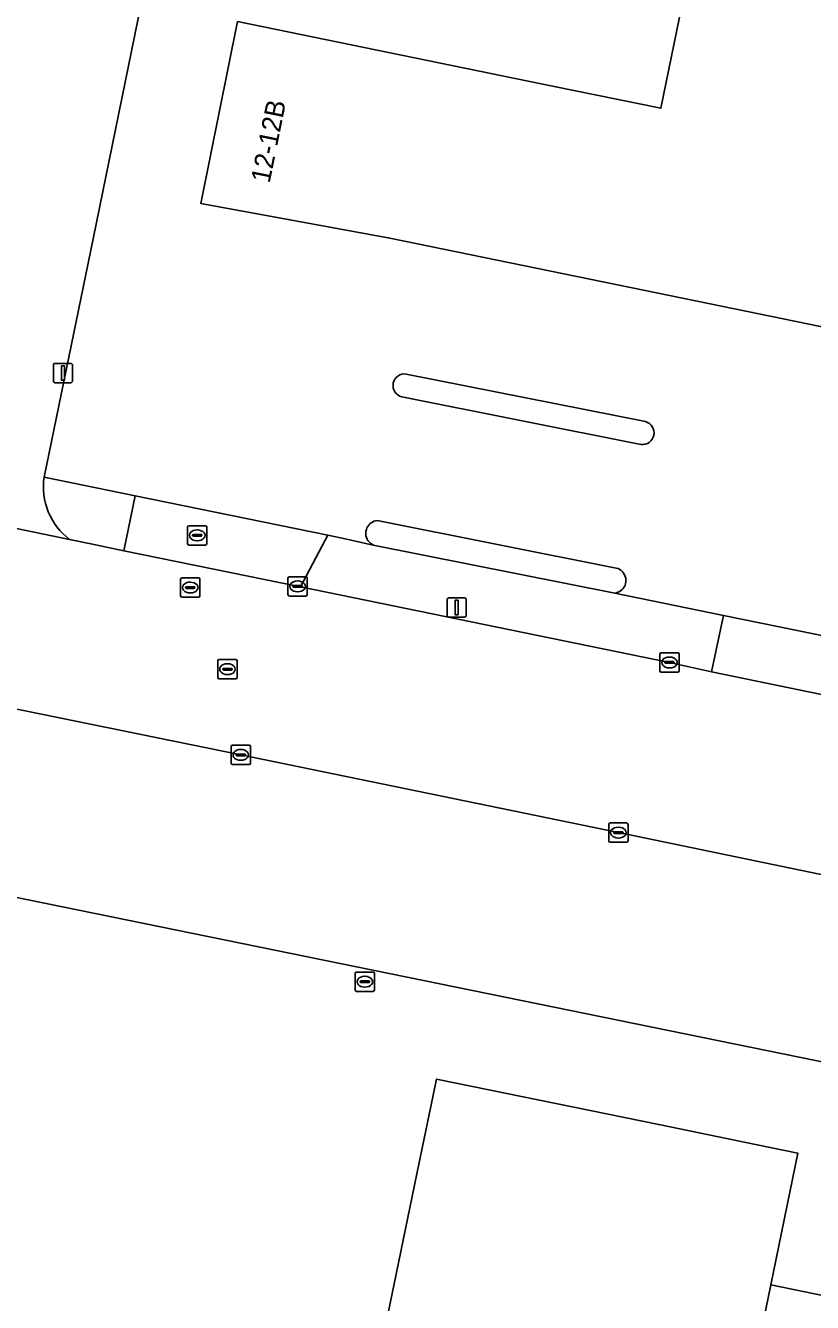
# Model space of a CAD drawing. Extents: x 157692 to 159674, y 381452 to 383291.
# Drawn here: x 158709.4 to 158750.1, y 382274.1 to 382340.2 of the extents above; entities that cross this region are included whole.
import ezdxf

# ---------------------------------------------------------------- set-up
doc = ezdxf.new("R2010")
doc.units = 0
for name, color, linetype in [('IMGEO_Brandkraan', 7, 'Continuous'), ('IMGEO_Erf', 7, 'Continuous'), ('IMGEO_Kolk', 7, 'Continuous'), ('IMGEO_Lichtmast', 7, 'Continuous'), ('IMGEO_Pand', 7, 'Continuous'), ('IMGEO_Pand_nummerreeks', 7, 'Continuous'), ('IMGEO_Rijbaan_lokaal_open', 7, 'Continuous'), ('IMGEO_Rioolput', 7, 'Continuous'), ('IMGEO_Verkeerseiland_open', 7, 'Continuous'), ('IMGEO_Voetpad_open', 7, 'Continuous')]:
    doc.layers.add(name, color=color, linetype=linetype)

msp = doc.modelspace()

# ---------------------------------------------------------------- linework, layer by layer
at = {"layer": 'IMGEO_Brandkraan'}
for p, q in [((158717.808, 382313.38), (158717.808, 382314.232)), ((158717.883, 382314.306), (158718.735, 382314.306)), ((158718.809, 382314.232), (158718.809, 382313.38)), ((158718.067, 382313.8), (158718.067, 382313.812)), ((158718.505, 382313.763), (158718.107, 382313.763)), ((158718.11, 382313.849), (158718.508, 382313.849)), ((158718.319, 382313.526), (158718.294, 382313.526)), ((158718.296, 382314.086), (158718.321, 382314.086)), ((158718.551, 382313.812), (158718.551, 382313.8)), ((158718.735, 382313.306), (158717.883, 382313.306))]:
    msp.add_line(p, q, dxfattribs=at)
for points in [[(158717.808, 382313.38), (158717.808, 382314.232)], [(158717.883, 382314.306), (158718.735, 382314.306)], [(158718.809, 382314.232), (158718.809, 382313.38)], [(158718.735, 382313.306), (158717.883, 382313.306)]]:
    msp.add_lwpolyline(points, dxfattribs=at)
for centre, radius, start, end in [((158717.885, 382314.23), 0.0765, 91.55205, 178.44795), ((158717.885, 382314.23), 0.0765, 91.55205, 178.44795), ((158718.733, 382314.23), 0.0765, 1.55205, 88.44795), ((158718.733, 382314.23), 0.0765, 1.55205, 88.44795), ((158718.107, 382313.809), 0.0403, 85.87752, 175.75265), ((158718.104, 382313.799), 0.0366, 178.93798, 274.71019), ((158718.508, 382313.806), 0.043, 264.86636, 352.45326), ((158718.512, 382313.811), 0.0386, 1.73085, 96.63898), ((158717.885, 382313.382), 0.0765, 181.55205, 268.44795), ((158717.885, 382313.382), 0.0765, 181.55205, 268.44795), ((158718.733, 382313.382), 0.0765, 271.55205, 358.44795), ((158718.733, 382313.382), 0.0765, 271.55205, 358.44795)]:
    msp.add_arc(centre, radius, start, end, dxfattribs=at)
for centre, major_axis, ratio, start_param, end_param in [((158718.295, 382313.806), (-0.387, 0.002), 0.722429, 4.712389, 7.853982), ((158718.32, 382313.806), (-0.39, 0.002), 0.717154, 1.570796, 4.712389)]:
    msp.add_ellipse(centre, major_axis=major_axis, ratio=ratio, start_param=start_param, end_param=end_param, dxfattribs=at)
at = {"layer": 'IMGEO_Erf'}
for points in [[(158720.044, 382364.008), (158712.928, 382329.134), (158710.395, 382316.819), (158715.098, 382315.854), (158725.053, 382313.813), (158725.797, 382313.66), (158727.41, 382313.293)], [(158766.252, 382340.884), (158764.298, 382331.343), (158768.72, 382330.438), (158767.848, 382326.179), (158766.845, 382321.28), (158762.998, 382322.068), (158763.854, 382326.248), (158755.16, 382328.028), (158754.302, 382323.838), (158744.14, 382325.919), (158728.259, 382329.17), (158718.497, 382330.96), (158720.398, 382340.369)], [(158729.115, 382322.147), (158741.475, 382319.685)], [(158741.24, 382318.508), (158728.88, 382320.97)], [(158703.868, 382232.929), (158737.91, 382225.935), (158740.836, 382240.44), (158722.149, 382244.289), (158723.325, 382250), (158729.667, 382280.789), (158730.675, 382285.686), (158742.158, 382283.335), (158747.254, 382282.292), (158749.35, 382281.863), (158747.95, 382275.046), (158756.482, 382273.294), (158758.758, 382284.334), (158774.797, 382281.051), (158774.915, 382281.626), (158583.923, 382320.599)], [(158727.607, 382314.575), (158739.967, 382312.114)], [(158739.897, 382310.815), (158745.516, 382309.667), (158754.049, 382307.922), (158763.74, 382305.941), (158825.695, 382293.283), (158865.561, 382285.172), (158872.186, 382283.72), (158876.329, 382282.962), (158882.131, 382281.773), (158888.158, 382280.537), (158988.039, 382260.114), (159000, 382257.67), (159006.103, 382256.423), (159011.658, 382255.288), (159018.046, 382253.981), (159023.028, 382252.988), (159037.803, 382250), (159039.91, 382249.574), (159043.144, 382248.92), (159043.356, 382248.877), (159043.484, 382248.846), (159053.13, 382246.78), (159055.84, 382246.213), (159072.286, 382242.773)]]:
    msp.add_lwpolyline(points, dxfattribs=at)
for centre, radius, start, end in [((158729.028, 382321.552), 0.601, 81.70547, 255.71211), ((158741.32, 382319.104), 0.601, 262.31937, 75.09822), ((158727.691, 382313.906), 0.674, 97.15339, 212.90377), ((158728.126, 382314.407), 1.324, 220.89476, 237.27648), ((158739.805, 382311.471), 0.663, 305.17046, 75.86444), ((158739.665, 382311.832), 1.043, 282.87012, 300.0498)]:
    msp.add_arc(centre, radius, start, end, dxfattribs=at)
at = {"layer": 'IMGEO_Kolk'}
for p, q in [((158722.996, 382310.741), (158722.996, 382311.593)), ((158723.071, 382311.667), (158723.923, 382311.667)), ((158723.997, 382311.593), (158723.997, 382310.741)), ((158723.255, 382311.161), (158723.255, 382311.173)), ((158723.693, 382311.124), (158723.295, 382311.124)), ((158723.298, 382311.21), (158723.696, 382311.21)), ((158723.507, 382310.887), (158723.482, 382310.887)), ((158723.484, 382311.447), (158723.509, 382311.447)), ((158723.739, 382311.173), (158723.739, 382311.161)), ((158723.923, 382310.667), (158723.071, 382310.667)), ((158742.218, 382306.806), (158742.218, 382307.658)), ((158742.293, 382307.732), (158743.145, 382307.732)), ((158743.219, 382307.658), (158743.219, 382306.806)), ((158742.477, 382307.226), (158742.477, 382307.238)), ((158742.915, 382307.189), (158742.517, 382307.189)), ((158742.52, 382307.275), (158742.918, 382307.275)), ((158742.729, 382306.952), (158742.704, 382306.952)), ((158742.706, 382307.512), (158742.731, 382307.512)), ((158742.961, 382307.238), (158742.961, 382307.226)), ((158743.145, 382306.732), (158742.293, 382306.732)), ((158720.132, 382302.955), (158720.984, 382302.955)), ((158720.057, 382302.029), (158720.057, 382302.881)), ((158720.316, 382302.449), (158720.316, 382302.461)), ((158720.754, 382302.412), (158720.356, 382302.412)), ((158720.359, 382302.498), (158720.757, 382302.498)), ((158720.545, 382302.735), (158720.57, 382302.735)), ((158720.8, 382302.461), (158720.8, 382302.449)), ((158721.058, 382302.881), (158721.058, 382302.029)), ((158720.984, 382301.955), (158720.132, 382301.955)), ((158720.568, 382302.175), (158720.543, 382302.175)), ((158739.575, 382298.008), (158739.575, 382298.86)), ((158739.65, 382298.934), (158740.502, 382298.934)), ((158739.834, 382298.428), (158739.834, 382298.44)), ((158740.272, 382298.391), (158739.874, 382298.391)), ((158739.877, 382298.477), (158740.275, 382298.477)), ((158740.063, 382298.714), (158740.088, 382298.714)), ((158740.318, 382298.44), (158740.318, 382298.428)), ((158740.576, 382298.86), (158740.576, 382298.008)), ((158740.502, 382297.934), (158739.65, 382297.934)), ((158740.086, 382298.154), (158740.061, 382298.154))]:
    msp.add_line(p, q, dxfattribs=at)
for points in [[(158722.996, 382310.741), (158722.996, 382311.593)], [(158723.071, 382311.667), (158723.923, 382311.667)], [(158723.997, 382311.593), (158723.997, 382310.741)], [(158723.923, 382310.667), (158723.071, 382310.667)], [(158742.218, 382306.806), (158742.218, 382307.658)], [(158742.293, 382307.732), (158743.145, 382307.732)], [(158743.219, 382307.658), (158743.219, 382306.806)], [(158743.145, 382306.732), (158742.293, 382306.732)], [(158720.132, 382302.955), (158720.984, 382302.955)], [(158720.057, 382302.029), (158720.057, 382302.881)], [(158721.058, 382302.881), (158721.058, 382302.029)], [(158720.984, 382301.955), (158720.132, 382301.955)], [(158739.575, 382298.008), (158739.575, 382298.86)], [(158739.65, 382298.934), (158740.502, 382298.934)], [(158740.576, 382298.86), (158740.576, 382298.008)], [(158740.502, 382297.934), (158739.65, 382297.934)]]:
    msp.add_lwpolyline(points, dxfattribs=at)
for centre, radius, start, end in [((158723.073, 382311.591), 0.0765, 91.55205, 178.44795), ((158723.073, 382311.591), 0.0765, 91.55205, 178.44795), ((158723.921, 382311.591), 0.0765, 1.55205, 88.44795), ((158723.921, 382311.591), 0.0765, 1.55205, 88.44795), ((158723.295, 382311.17), 0.0403, 85.87752, 175.75265), ((158723.292, 382311.16), 0.0366, 178.93798, 274.71019), ((158723.696, 382311.167), 0.043, 264.86636, 352.45326), ((158723.7, 382311.172), 0.0386, 1.73085, 96.63898), ((158723.073, 382310.743), 0.0765, 181.55205, 268.44795), ((158723.073, 382310.743), 0.0765, 181.55205, 268.44795), ((158723.921, 382310.743), 0.0765, 271.55205, 358.44795), ((158723.921, 382310.743), 0.0765, 271.55205, 358.44795), ((158742.295, 382307.656), 0.0765, 91.55205, 178.44795), ((158742.295, 382307.656), 0.0765, 91.55205, 178.44795), ((158743.143, 382307.656), 0.0765, 1.55205, 88.44795), ((158743.143, 382307.656), 0.0765, 1.55205, 88.44795), ((158742.517, 382307.235), 0.0403, 85.87752, 175.75265), ((158742.514, 382307.225), 0.0366, 178.93798, 274.71019), ((158742.918, 382307.232), 0.043, 264.86636, 352.45326), ((158742.922, 382307.237), 0.0386, 1.73085, 96.63898), ((158742.295, 382306.808), 0.0765, 181.55205, 268.44795), ((158742.295, 382306.808), 0.0765, 181.55205, 268.44795), ((158743.143, 382306.808), 0.0765, 271.55205, 358.44795), ((158743.143, 382306.808), 0.0765, 271.55205, 358.44795), ((158720.134, 382302.879), 0.0765, 91.55205, 178.44795), ((158720.134, 382302.879), 0.0765, 91.55205, 178.44795), ((158720.982, 382302.879), 0.0765, 1.55205, 88.44795), ((158720.982, 382302.879), 0.0765, 1.55205, 88.44795), ((158720.356, 382302.458), 0.0403, 85.87752, 175.75265), ((158720.353, 382302.448), 0.0366, 178.93798, 274.71019), ((158720.757, 382302.455), 0.043, 264.86636, 352.45326), ((158720.761, 382302.46), 0.0386, 1.73085, 96.63898), ((158720.134, 382302.031), 0.0765, 181.55205, 268.44795), ((158720.134, 382302.031), 0.0765, 181.55205, 268.44795), ((158720.982, 382302.031), 0.0765, 271.55205, 358.44795), ((158720.982, 382302.031), 0.0765, 271.55205, 358.44795), ((158739.652, 382298.858), 0.0765, 91.55205, 178.44795), ((158739.652, 382298.858), 0.0765, 91.55205, 178.44795), ((158739.874, 382298.437), 0.0403, 85.87752, 175.75265), ((158739.871, 382298.427), 0.0366, 178.93798, 274.71019), ((158740.275, 382298.434), 0.043, 264.86636, 352.45326), ((158740.279, 382298.439), 0.0386, 1.73085, 96.63898), ((158740.5, 382298.858), 0.0765, 1.55205, 88.44795), ((158740.5, 382298.858), 0.0765, 1.55205, 88.44795), ((158739.652, 382298.01), 0.0765, 181.55205, 268.44795), ((158739.652, 382298.01), 0.0765, 181.55205, 268.44795), ((158740.5, 382298.01), 0.0765, 271.55205, 358.44795), ((158740.5, 382298.01), 0.0765, 271.55205, 358.44795)]:
    msp.add_arc(centre, radius, start, end, dxfattribs=at)
for centre, major_axis, ratio, start_param, end_param in [((158723.483, 382311.167), (-0.387, 0.002), 0.722429, 4.712389, 7.853982), ((158723.508, 382311.167), (-0.39, 0.002), 0.717154, 1.570796, 4.712389), ((158742.705, 382307.232), (-0.387, 0.002), 0.722429, 4.712389, 7.853982), ((158742.73, 382307.232), (-0.39, 0.002), 0.717154, 1.570796, 4.712389), ((158720.544, 382302.455), (-0.387, 0.002), 0.722429, 4.712389, 7.853982), ((158720.569, 382302.455), (-0.39, 0.002), 0.717154, 1.570796, 4.712389), ((158740.062, 382298.434), (-0.387, 0.002), 0.722429, 4.712389, 7.853982), ((158740.087, 382298.434), (-0.39, 0.002), 0.717154, 1.570796, 4.712389)]:
    msp.add_ellipse(centre, major_axis=major_axis, ratio=ratio, start_param=start_param, end_param=end_param, dxfattribs=at)
at = {"layer": 'IMGEO_Lichtmast'}
for p, q in [((158710.874, 382321.797), (158710.874, 382322.597)), ((158710.874, 382322.597), (158710.874, 382321.797)), ((158710.974, 382322.697), (158711.764, 382322.697)), ((158711.764, 382322.697), (158710.974, 382322.697)), ((158711.864, 382322.597), (158711.864, 382321.797)), ((158711.864, 382321.797), (158711.864, 382322.597)), ((158711.764, 382321.697), (158710.974, 382321.697)), ((158710.974, 382321.697), (158711.764, 382321.697)), ((158731.223, 382309.676), (158731.223, 382310.476)), ((158731.223, 382310.476), (158731.223, 382309.676)), ((158731.323, 382310.576), (158732.113, 382310.576)), ((158732.113, 382310.576), (158731.323, 382310.576)), ((158732.213, 382310.476), (158732.213, 382309.676)), ((158732.213, 382309.676), (158732.213, 382310.476)), ((158732.113, 382309.576), (158731.323, 382309.576)), ((158731.323, 382309.576), (158732.113, 382309.576))]:
    msp.add_line(p, q, dxfattribs=at)
for points in [[(158711.294, 382322.572), (158711.444, 382322.572), (158711.444, 382321.822), (158711.294, 382321.822), (158711.294, 382322.572)], [(158731.643, 382310.451), (158731.793, 382310.451), (158731.793, 382309.701), (158731.643, 382309.701), (158731.643, 382310.451)]]:
    msp.add_lwpolyline(points, dxfattribs=at)
for centre, start, end in [((158710.974, 382322.597), 90, 180), ((158710.974, 382322.597), 90, 180), ((158711.764, 382322.597), 0, 90), ((158711.764, 382322.597), 360, 90), ((158710.974, 382321.797), 180, 270), ((158710.974, 382321.797), 180, 270), ((158711.764, 382321.797), 270, 0), ((158711.764, 382321.797), 270, 0), ((158731.323, 382310.476), 90, 180), ((158731.323, 382310.476), 90, 180), ((158732.113, 382310.476), 0, 90), ((158732.113, 382310.476), 360, 90), ((158731.323, 382309.676), 180, 270), ((158731.323, 382309.676), 180, 270), ((158732.113, 382309.676), 270, 0), ((158732.113, 382309.676), 270, 0)]:
    msp.add_arc(centre, 0.1, start, end, dxfattribs=at)
at = {"layer": 'IMGEO_Pand'}
for points in [[(158766.252, 382340.884), (158744.215, 382345.401), (158742.265, 382335.888), (158736.753, 382337.018), (158720.398, 382340.369), (158718.497, 382330.96), (158728.259, 382329.17), (158744.14, 382325.919), (158754.302, 382323.838), (158755.16, 382328.028), (158763.854, 382326.248), (158762.998, 382322.068), (158766.845, 382321.28), (158767.848, 382326.179), (158768.72, 382330.438), (158764.298, 382331.343)], [(158747.95, 382275.046), (158749.35, 382281.863), (158747.254, 382282.292), (158742.158, 382283.335), (158730.675, 382285.686), (158729.667, 382280.789), (158723.325, 382250), (158722.149, 382244.289), (158740.836, 382240.44), (158742.801, 382250), (158744.243, 382257.017)], [(158747.95, 382275.046), (158744.243, 382257.017), (158752.766, 382255.271), (158752.1, 382252.041), (158762.079, 382250), (158768.445, 382248.698), (158768.711, 382250), (158774.171, 382276.675), (158775.174, 382281.573), (158774.915, 382281.626), (158774.797, 382281.051), (158758.758, 382284.334), (158756.482, 382273.294)]]:
    msp.add_lwpolyline(points, close=True, dxfattribs=at)
msp.add_lwpolyline([(158720.398, 382340.369), (158736.753, 382337.018), (158742.265, 382335.888), (158744.215, 382345.401)], dxfattribs=at)
at = {"layer": 'IMGEO_Rijbaan_lokaal_open'}
for points in [[(158710.395, 382316.819), (158712.928, 382329.134), (158720.044, 382364.008), (158727.797, 382402.142), (158727.926, 382402.123), (158727.994, 382402.424), (158729.812, 382411.517), (158710.107, 382415.583), (158708.423, 382407.414), (158706.448, 382397.829), (158702.694, 382379.617), (158699.065, 382362.008), (158696.064, 382347.447), (158695.197, 382343.266), (158691.802, 382326.896), (158690.748, 382320.985), (158691.021, 382320.929), (158693.858, 382320.35)], [(158744.89, 382306.754), (158742.717, 382307.23), (158723.644, 382311.136), (158714.521, 382313.011), (158712.813, 382313.362), (158711.707, 382313.592), (158693.337, 382317.409), (158651.257, 382326.067), (158639.414, 382328.503), (158630.487, 382330.34), (158617.947, 382332.92), (158590.277, 382338.612), (158586.837, 382339.353), (158586.676, 382339.386), (158584.918, 382330.64)], [(158585.369, 382330.295), (158606.304, 382326.032), (158627.099, 382321.705), (158645.918, 382317.846), (158664.706, 382313.983), (158683.357, 382310.127), (158703.229, 382305.989), (158720.558, 382302.454), (158740.076, 382298.433), (158761.28, 382294.05), (158776.976, 382290.837), (158783.229, 382289.567), (158794.751, 382287.205), (158799.061, 382286.324), (158819.844, 382282.089), (158838.842, 382278.204), (158844.942, 382276.94), (158852.145, 382275.448)], [(158693.337, 382317.409), (158711.707, 382313.592)], [(158859.681, 382283.22), (158840.554, 382287.183), (158825.094, 382290.327), (158820.213, 382291.319), (158800.497, 382295.362), (158780.293, 382299.514), (158763.168, 382302.997), (158761.821, 382303.271), (158753.419, 382304.996), (158744.89, 382306.754)]]:
    msp.add_lwpolyline(points, dxfattribs=at)
msp.add_arc((158713.767, 382316.31), 3.41, 171.41073, 232.8396, dxfattribs=at)
at = {"layer": 'IMGEO_Rioolput'}
for p, q in [((158717.447, 382310.68), (158717.447, 382311.532)), ((158717.522, 382311.606), (158718.374, 382311.606)), ((158718.448, 382311.532), (158718.448, 382310.68)), ((158717.706, 382311.1), (158717.706, 382311.112)), ((158718.144, 382311.063), (158717.746, 382311.063)), ((158717.749, 382311.149), (158718.147, 382311.149)), ((158717.935, 382311.386), (158717.96, 382311.386)), ((158718.19, 382311.112), (158718.19, 382311.1)), ((158718.374, 382310.606), (158717.522, 382310.606)), ((158717.958, 382310.826), (158717.933, 382310.826)), ((158719.371, 382306.459), (158719.371, 382307.311)), ((158719.446, 382307.385), (158720.298, 382307.385)), ((158719.63, 382306.879), (158719.63, 382306.891)), ((158719.673, 382306.928), (158720.071, 382306.928)), ((158719.859, 382307.165), (158719.884, 382307.165)), ((158720.114, 382306.891), (158720.114, 382306.879)), ((158720.372, 382307.311), (158720.372, 382306.459)), ((158720.298, 382306.385), (158719.446, 382306.385)), ((158720.068, 382306.842), (158719.67, 382306.842)), ((158719.882, 382306.605), (158719.857, 382306.605)), ((158726.471, 382290.299), (158726.471, 382291.151)), ((158726.546, 382291.225), (158727.398, 382291.225)), ((158727.472, 382291.151), (158727.472, 382290.299)), ((158726.73, 382290.719), (158726.73, 382290.731)), ((158727.168, 382290.682), (158726.77, 382290.682)), ((158726.773, 382290.768), (158727.171, 382290.768)), ((158726.982, 382290.445), (158726.957, 382290.445)), ((158726.959, 382291.005), (158726.984, 382291.005)), ((158727.214, 382290.731), (158727.214, 382290.719)), ((158727.398, 382290.225), (158726.546, 382290.225))]:
    msp.add_line(p, q, dxfattribs=at)
for points in [[(158717.447, 382310.68), (158717.447, 382311.532)], [(158717.522, 382311.606), (158718.374, 382311.606)], [(158718.448, 382311.532), (158718.448, 382310.68)], [(158718.374, 382310.606), (158717.522, 382310.606)], [(158719.371, 382306.459), (158719.371, 382307.311)], [(158719.446, 382307.385), (158720.298, 382307.385)], [(158720.372, 382307.311), (158720.372, 382306.459)], [(158720.298, 382306.385), (158719.446, 382306.385)], [(158726.471, 382290.299), (158726.471, 382291.151)], [(158726.546, 382291.225), (158727.398, 382291.225)], [(158727.472, 382291.151), (158727.472, 382290.299)], [(158727.398, 382290.225), (158726.546, 382290.225)]]:
    msp.add_lwpolyline(points, dxfattribs=at)
for centre, radius, start, end in [((158717.524, 382311.53), 0.0765, 91.55205, 178.44795), ((158717.524, 382311.53), 0.0765, 91.55205, 178.44795), ((158718.372, 382311.53), 0.0765, 1.55205, 88.44795), ((158718.372, 382311.53), 0.0765, 1.55205, 88.44795), ((158717.746, 382311.109), 0.0403, 85.87752, 175.75265), ((158717.743, 382311.099), 0.0366, 178.93798, 274.71019), ((158718.147, 382311.106), 0.043, 264.86636, 352.45326), ((158718.151, 382311.111), 0.0386, 1.73085, 96.63898), ((158717.524, 382310.682), 0.0765, 181.55205, 268.44795), ((158717.524, 382310.682), 0.0765, 181.55205, 268.44795), ((158718.372, 382310.682), 0.0765, 271.55205, 358.44795), ((158718.372, 382310.682), 0.0765, 271.55205, 358.44795), ((158719.448, 382307.309), 0.0765, 91.55205, 178.44795), ((158719.448, 382307.309), 0.0765, 91.55205, 178.44795), ((158719.67, 382306.888), 0.0403, 85.87752, 175.75265), ((158720.075, 382306.89), 0.0386, 1.73085, 96.63898), ((158720.296, 382307.309), 0.0765, 1.55205, 88.44795), ((158720.296, 382307.309), 0.0765, 1.55205, 88.44795), ((158719.448, 382306.461), 0.0765, 181.55205, 268.44795), ((158719.448, 382306.461), 0.0765, 181.55205, 268.44795), ((158719.667, 382306.878), 0.0366, 178.93798, 274.71019), ((158720.071, 382306.885), 0.043, 264.86636, 352.45326), ((158720.296, 382306.461), 0.0765, 271.55205, 358.44795), ((158720.296, 382306.461), 0.0765, 271.55205, 358.44795), ((158726.548, 382291.149), 0.0765, 91.55205, 178.44795), ((158726.548, 382291.149), 0.0765, 91.55205, 178.44795), ((158727.396, 382291.149), 0.0765, 1.55205, 88.44795), ((158727.396, 382291.149), 0.0765, 1.55205, 88.44795), ((158726.77, 382290.728), 0.0403, 85.87752, 175.75265), ((158726.767, 382290.718), 0.0366, 178.93798, 274.71019), ((158727.171, 382290.725), 0.043, 264.86636, 352.45326), ((158727.175, 382290.73), 0.0386, 1.73085, 96.63898), ((158726.548, 382290.301), 0.0765, 181.55205, 268.44795), ((158726.548, 382290.301), 0.0765, 181.55205, 268.44795), ((158727.396, 382290.301), 0.0765, 271.55205, 358.44795), ((158727.396, 382290.301), 0.0765, 271.55205, 358.44795)]:
    msp.add_arc(centre, radius, start, end, dxfattribs=at)
for centre, major_axis, ratio, start_param, end_param in [((158717.934, 382311.106), (-0.387, 0.002), 0.722429, 4.712389, 7.853982), ((158717.959, 382311.106), (-0.39, 0.002), 0.717154, 1.570796, 4.712389), ((158719.858, 382306.885), (-0.387, 0.002), 0.722429, 4.712389, 7.853982), ((158719.883, 382306.885), (-0.39, 0.002), 0.717154, 1.570796, 4.712389), ((158726.958, 382290.725), (-0.387, 0.002), 0.722429, 4.712389, 7.853982), ((158726.983, 382290.725), (-0.39, 0.002), 0.717154, 1.570796, 4.712389)]:
    msp.add_ellipse(centre, major_axis=major_axis, ratio=ratio, start_param=start_param, end_param=end_param, dxfattribs=at)
at = {"layer": 'IMGEO_Verkeerseiland_open'}
for points in [[(158741.475, 382319.685), (158729.115, 382322.147)], [(158728.88, 382320.97), (158741.24, 382318.508)], [(158739.967, 382312.114), (158727.607, 382314.575)], [(158727.41, 382313.293), (158739.897, 382310.815)]]:
    msp.add_lwpolyline(points, dxfattribs=at)
for centre, radius, start, end in [((158729.028, 382321.552), 0.601, 81.70547, 255.71211), ((158741.32, 382319.104), 0.601, 262.31937, 75.09822), ((158727.691, 382313.906), 0.674, 97.15339, 212.90377), ((158728.126, 382314.407), 1.324, 220.89476, 237.27648), ((158739.805, 382311.471), 0.663, 305.17046, 75.86444), ((158739.665, 382311.832), 1.043, 282.87012, 300.0498)]:
    msp.add_arc(centre, radius, start, end, dxfattribs=at)
at = {"layer": 'IMGEO_Voetpad_open'}
for points in [[(158776.976, 382290.837), (158761.28, 382294.05), (158740.076, 382298.433), (158720.558, 382302.454), (158703.229, 382305.989), (158683.357, 382310.127), (158664.706, 382313.983), (158645.918, 382317.846), (158627.099, 382321.705), (158606.304, 382326.032), (158585.369, 382330.295)], [(158585.636, 382328.823), (158583.923, 382320.599), (158774.915, 382281.626), (158775.174, 382281.573), (158776.28, 382289.179), (158776.115, 382289.213), (158776.367, 382290.437)], [(158711.707, 382313.592), (158712.813, 382313.362), (158714.521, 382313.011), (158715.098, 382315.854), (158710.395, 382316.819)]]:
    msp.add_lwpolyline(points, dxfattribs=at)
for points in [[(158723.644, 382311.136), (158725.053, 382313.813), (158715.098, 382315.854), (158714.521, 382313.011)], [(158739.897, 382310.815), (158727.41, 382313.293), (158725.797, 382313.66), (158725.053, 382313.813), (158723.644, 382311.136), (158742.717, 382307.23), (158744.89, 382306.754), (158745.516, 382309.667)], [(158745.516, 382309.667), (158744.89, 382306.754), (158753.419, 382304.996), (158754.049, 382307.922)]]:
    msp.add_lwpolyline(points, close=True, dxfattribs=at)
msp.add_arc((158713.767, 382316.31), 3.41, 171.41073, 232.8396, dxfattribs=at)

# ---------------------------------------------------------------- texts
at = {"layer": 'IMGEO_Pand_nummerreeks'}
msp.add_text('12-12B', height=1, rotation=78.57769, dxfattribs=at).set_placement((158722.049, 382331.98))

doc.saveas('drawing.dxf')
